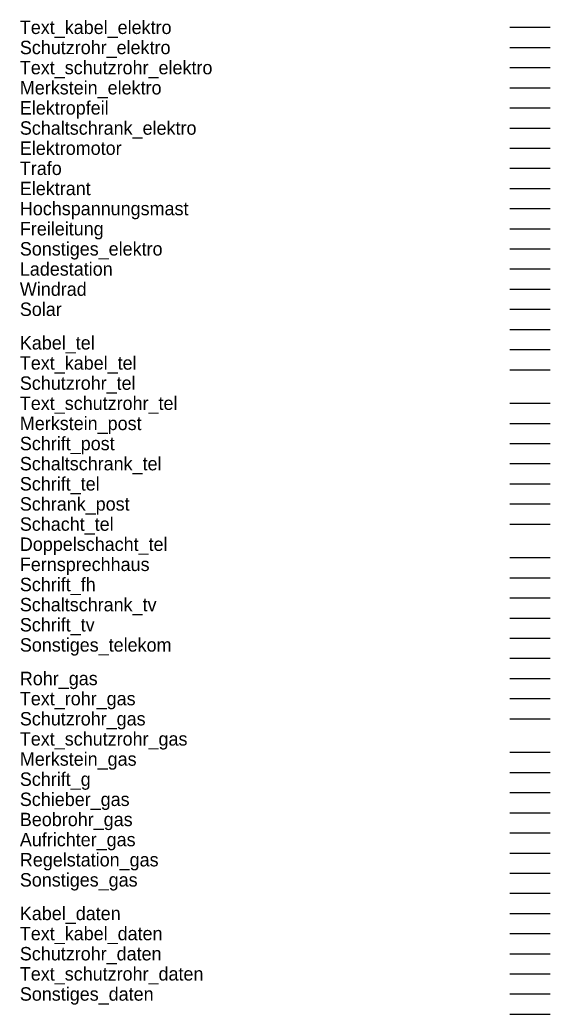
# Model space of a CAD drawing. Extents: x 0 to 177, y -135 to 1.
# Drawn here: x 83.5 to 123, y -133 to -58.9 of the extents above; entities that cross this region are included whole.
import ezdxf

# ---------------------------------------------------------------- set-up
doc = ezdxf.new("R2010")
doc.units = 0
for name, color, linetype in [('Ampel', 7, 'Continuous'), ('Aufrichter_gas', 7, 'Continuous'), ('Beobrohr_gas', 7, 'Continuous'), ('Bodenleuchte', 7, 'Continuous'), ('Doppelschacht_fw', 7, 'Continuous'), ('Doppelschacht_tel', 7, 'Continuous'), ('Elektrant', 7, 'Continuous'), ('Elektromotor', 7, 'Continuous'), ('Elektropfeil', 7, 'Continuous'), ('Fernsprechhaus', 7, 'Continuous'), ('Freileitung', 7, 'Continuous'), ('Haengelampe', 7, 'Continuous'), ('Hochspannungsmast', 7, 'Continuous'), ('Hoehe_el_symbol', 7, 'Continuous'), ('Hoehe_el_zahl', 7, 'Continuous'), ('Hoehe_first_symbol', 7, 'Continuous'), ('Hoehe_first_zahl', 7, 'Continuous'), ('Hoehe_objekt_zahl', 7, 'Continuous'), ('Hoehe_tel_symbol', 7, 'Continuous'), ('Hoehe_tel_zahl', 7, 'Continuous'), ('Hoehe_trauf_symbol', 7, 'Continuous'), ('Hoehe_trauf_zahl', 7, 'Continuous'), ('Hoehe_wasser_symbol', 7, 'Continuous'), ('Hoehe_wasser_zahl', 7, 'Continuous'), ('Hoehenpunkt_symbol', 7, 'Continuous'), ('Hoehenpunkt_zahl', 7, 'Continuous'), ('Kabel_daten', 7, 'Continuous'), ('Kabel_leucht', 7, 'Continuous'), ('Kabel_lsa', 7, 'Continuous'), ('Kabel_tel', 7, 'Continuous'), ('Ladestation', 7, 'Continuous'), ('Lampe_betonmast', 7, 'Continuous'), ('Lampe_holzmast', 7, 'Continuous'), ('Lampe_plastemast', 7, 'Continuous'), ('Lampe_stahlgittermast', 7, 'Continuous'), ('Lampe_stahlrohrmast', 7, 'Continuous'), ('Lampennummer', 7, 'Continuous'), ('Merkstein_elektro', 7, 'Continuous'), ('Merkstein_gas', 7, 'Continuous'), ('Merkstein_post', 7, 'Continuous'), ('Objektlampe', 7, 'Continuous'), ('Profil', 7, 'Continuous'), ('Regelstation_gas', 7, 'Continuous'), ('Rohr_brauchw', 7, 'Continuous'), ('Rohr_gas', 7, 'Continuous'), ('Rohr_ueber_fw', 7, 'Continuous'), ('Rohr_ueber_fw_text', 7, 'Continuous'), ('Rohr_unter_fw', 7, 'Continuous'), ('Rohr_unter_fw_text', 7, 'Continuous'), ('Schacht_e_fw', 7, 'Continuous'), ('Schacht_e_lsa', 7, 'Continuous'), ('Schacht_tel', 7, 'Continuous'), ('Schaltschrank_elektro', 7, 'Continuous'), ('Schaltschrank_leucht', 7, 'Continuous'), ('Schaltschrank_leucht_nr', 7, 'Continuous'), ('Schaltschrank_tel', 7, 'Continuous'), ('Schaltschrank_tv', 7, 'Continuous'), ('Schieber_fw', 7, 'Continuous'), ('Schieber_gas', 7, 'Continuous'), ('Schrank_post', 7, 'Continuous'), ('Schrift_fh', 7, 'Continuous'), ('Schrift_fw', 7, 'Continuous'), ('Schrift_g', 7, 'Continuous'), ('Schrift_lsa', 7, 'Continuous'), ('Schrift_post', 7, 'Continuous'), ('Schrift_tel', 7, 'Continuous'), ('Schrift_tv', 7, 'Continuous'), ('Schutzrohr_daten', 7, 'Continuous'), ('Schutzrohr_elektro', 7, 'Continuous'), ('Schutzrohr_gas', 7, 'Continuous'), ('Schutzrohr_leucht', 7, 'Continuous'), ('Schutzrohr_lsa', 7, 'Continuous'), ('Schutzrohr_tel', 7, 'Continuous'), ('Solar', 7, 'Continuous'), ('Sonstiges_daten', 7, 'Continuous'), ('Sonstiges_elektro', 7, 'Continuous'), ('Sonstiges_fw', 7, 'Continuous'), ('Sonstiges_gas', 7, 'Continuous'), ('Sonstiges_telekom', 7, 'Continuous'), ('Text_kabel_daten', 7, 'Continuous'), ('Text_kabel_elektro', 7, 'Continuous'), ('Text_kabel_leucht', 7, 'Continuous'), ('Text_kabel_lsa', 7, 'Continuous'), ('Text_kabel_tel', 7, 'Continuous'), ('Text_rohr_brauchw', 7, 'Continuous'), ('Text_rohr_gas', 7, 'Continuous'), ('Text_schutzrohr_daten', 7, 'Continuous'), ('Text_schutzrohr_elektro', 7, 'Continuous'), ('Text_schutzrohr_gas', 7, 'Continuous'), ('Text_schutzrohr_leucht', 7, 'Continuous'), ('Text_schutzrohr_lsa', 7, 'Continuous'), ('Text_schutzrohr_tel', 7, 'Continuous'), ('Trafo', 7, 'Continuous'), ('Wandlampe', 7, 'Continuous'), ('Windrad', 7, 'Continuous')]:
    doc.layers.add(name, color=color, linetype=linetype)

msp = doc.modelspace()

# ---------------------------------------------------------------- linework, layer by layer
at = {"layer": 'Ampel'}
msp.add_line((120, -96.5), (123, -96.5), dxfattribs=at)
at = {"layer": 'Bodenleuchte'}
msp.add_line((120, -79), (123, -79), dxfattribs=at)
at = {"layer": 'Doppelschacht_fw'}
msp.add_line((120, -106.5), (123, -106.5), dxfattribs=at)
at = {"layer": 'Haengelampe'}
msp.add_line((120, -80.5), (123, -80.5), dxfattribs=at)
at = {"layer": 'Hoehe_el_symbol'}
msp.add_line((120, -128.5), (123, -128.5), dxfattribs=at)
at = {"layer": 'Hoehe_el_zahl'}
msp.add_line((120, -130), (123, -130), dxfattribs=at)
at = {"layer": 'Hoehe_first_symbol'}
msp.add_line((120, -125.5), (123, -125.5), dxfattribs=at)
at = {"layer": 'Hoehe_first_zahl'}
msp.add_line((120, -127), (123, -127), dxfattribs=at)
at = {"layer": 'Hoehe_objekt_zahl'}
msp.add_line((120, -118), (123, -118), dxfattribs=at)
at = {"layer": 'Hoehe_tel_symbol'}
msp.add_line((120, -131.5), (123, -131.5), dxfattribs=at)
at = {"layer": 'Hoehe_tel_zahl'}
msp.add_line((120, -133), (123, -133), dxfattribs=at)
at = {"layer": 'Hoehe_trauf_symbol'}
msp.add_line((120, -122.5), (123, -122.5), dxfattribs=at)
at = {"layer": 'Hoehe_trauf_zahl'}
msp.add_line((120, -124), (123, -124), dxfattribs=at)
at = {"layer": 'Hoehe_wasser_symbol'}
msp.add_line((120, -119.5), (123, -119.5), dxfattribs=at)
at = {"layer": 'Hoehe_wasser_zahl'}
msp.add_line((120, -121), (123, -121), dxfattribs=at)
at = {"layer": 'Hoehenpunkt_symbol'}
msp.add_line((120, -115), (123, -115), dxfattribs=at)
at = {"layer": 'Hoehenpunkt_zahl'}
msp.add_line((120, -116.5), (123, -116.5), dxfattribs=at)
at = {"layer": 'Kabel_leucht'}
msp.add_line((120, -62.5), (123, -62.5), dxfattribs=at)
at = {"layer": 'Kabel_lsa'}
msp.add_line((120, -87.5), (123, -87.5), dxfattribs=at)
at = {"layer": 'Lampe_betonmast'}
msp.add_line((120, -71.5), (123, -71.5), dxfattribs=at)
at = {"layer": 'Lampe_holzmast'}
msp.add_line((120, -73), (123, -73), dxfattribs=at)
at = {"layer": 'Lampe_plastemast'}
msp.add_line((120, -77.5), (123, -77.5), dxfattribs=at)
at = {"layer": 'Lampe_stahlgittermast'}
msp.add_line((120, -76), (123, -76), dxfattribs=at)
at = {"layer": 'Lampe_stahlrohrmast'}
msp.add_line((120, -74.5), (123, -74.5), dxfattribs=at)
at = {"layer": 'Lampennummer'}
msp.add_line((120, -85), (123, -85), dxfattribs=at)
at = {"layer": 'Objektlampe'}
msp.add_line((120, -83.5), (123, -83.5), dxfattribs=at)
at = {"layer": 'Profil'}
msp.add_line((120, -113.5), (123, -113.5), dxfattribs=at)
at = {"layer": 'Rohr_brauchw'}
msp.add_line((120, -59.5), (123, -59.5), dxfattribs=at)
at = {"layer": 'Rohr_ueber_fw'}
msp.add_line((120, -99), (123, -99), dxfattribs=at)
at = {"layer": 'Rohr_ueber_fw_text'}
msp.add_line((120, -100.5), (123, -100.5), dxfattribs=at)
at = {"layer": 'Rohr_unter_fw'}
msp.add_line((120, -102), (123, -102), dxfattribs=at)
at = {"layer": 'Rohr_unter_fw_text'}
msp.add_line((120, -103.5), (123, -103.5), dxfattribs=at)
at = {"layer": 'Schacht_e_fw'}
msp.add_line((120, -105), (123, -105), dxfattribs=at)
at = {"layer": 'Schacht_e_lsa'}
msp.add_line((120, -93.5), (123, -93.5), dxfattribs=at)
at = {"layer": 'Schaltschrank_leucht'}
msp.add_line((120, -68.5), (123, -68.5), dxfattribs=at)
at = {"layer": 'Schaltschrank_leucht_nr'}
msp.add_line((120, -70), (123, -70), dxfattribs=at)
at = {"layer": 'Schieber_fw'}
msp.add_line((120, -109.5), (123, -109.5), dxfattribs=at)
at = {"layer": 'Schrift_fw'}
msp.add_line((120, -108), (123, -108), dxfattribs=at)
at = {"layer": 'Schrift_lsa'}
msp.add_line((120, -95), (123, -95), dxfattribs=at)
at = {"layer": 'Schutzrohr_leucht'}
msp.add_line((120, -65.5), (123, -65.5), dxfattribs=at)
at = {"layer": 'Schutzrohr_lsa'}
msp.add_line((120, -90.5), (123, -90.5), dxfattribs=at)
at = {"layer": 'Sonstiges_fw'}
msp.add_line((120, -111), (123, -111), dxfattribs=at)
at = {"layer": 'Text_kabel_leucht'}
msp.add_line((120, -64), (123, -64), dxfattribs=at)
at = {"layer": 'Text_kabel_lsa'}
msp.add_line((120, -89), (123, -89), dxfattribs=at)
at = {"layer": 'Text_rohr_brauchw'}
msp.add_line((120, -61), (123, -61), dxfattribs=at)
at = {"layer": 'Text_schutzrohr_leucht'}
msp.add_line((120, -67), (123, -67), dxfattribs=at)
at = {"layer": 'Text_schutzrohr_lsa'}
msp.add_line((120, -92), (123, -92), dxfattribs=at)
at = {"layer": 'Wandlampe'}
msp.add_line((120, -82), (123, -82), dxfattribs=at)

# ---------------------------------------------------------------- texts
at = {"layer": 'Aufrichter_gas'}
msp.add_text('Aufrichter_gas', height=1, dxfattribs=at).set_placement((83.5, -120.5))
at = {"layer": 'Beobrohr_gas'}
msp.add_text('Beobrohr_gas', height=1, dxfattribs=at).set_placement((83.5, -119))
at = {"layer": 'Doppelschacht_tel'}
msp.add_text('Doppelschacht_tel', height=1, dxfattribs=at).set_placement((83.5, -98.5))
at = {"layer": 'Elektrant'}
msp.add_text('Elektrant', height=1, dxfattribs=at).set_placement((83.5, -72))
at = {"layer": 'Elektromotor'}
msp.add_text('Elektromotor', height=1, dxfattribs=at).set_placement((83.5, -69))
at = {"layer": 'Elektropfeil'}
msp.add_text('Elektropfeil', height=1, dxfattribs=at).set_placement((83.5, -66))
at = {"layer": 'Fernsprechhaus'}
msp.add_text('Fernsprechhaus', height=1, dxfattribs=at).set_placement((83.5, -100))
at = {"layer": 'Freileitung'}
msp.add_text('Freileitung', height=1, dxfattribs=at).set_placement((83.5, -75))
at = {"layer": 'Hochspannungsmast'}
msp.add_text('Hochspannungsmast', height=1, dxfattribs=at).set_placement((83.5, -73.5))
at = {"layer": 'Kabel_daten'}
msp.add_text('Kabel_daten', height=1, dxfattribs=at).set_placement((83.5, -126))
at = {"layer": 'Kabel_tel'}
msp.add_text('Kabel_tel', height=1, dxfattribs=at).set_placement((83.5, -83.5))
at = {"layer": 'Ladestation'}
msp.add_text('Ladestation', height=1, dxfattribs=at).set_placement((83.5, -78))
at = {"layer": 'Merkstein_elektro'}
msp.add_text('Merkstein_elektro', height=1, dxfattribs=at).set_placement((83.5, -64.5))
at = {"layer": 'Merkstein_gas'}
msp.add_text('Merkstein_gas', height=1, dxfattribs=at).set_placement((83.5, -114.5))
at = {"layer": 'Merkstein_post'}
msp.add_text('Merkstein_post', height=1, dxfattribs=at).set_placement((83.5, -89.5))
at = {"layer": 'Regelstation_gas'}
msp.add_text('Regelstation_gas', height=1, dxfattribs=at).set_placement((83.5, -122))
at = {"layer": 'Rohr_gas'}
msp.add_text('Rohr_gas', height=1, dxfattribs=at).set_placement((83.5, -108.5))
at = {"layer": 'Schacht_tel'}
msp.add_text('Schacht_tel', height=1, dxfattribs=at).set_placement((83.5, -97))
at = {"layer": 'Schaltschrank_elektro'}
msp.add_text('Schaltschrank_elektro', height=1, dxfattribs=at).set_placement((83.5, -67.5))
at = {"layer": 'Schaltschrank_tel'}
msp.add_text('Schaltschrank_tel', height=1, dxfattribs=at).set_placement((83.5, -92.5))
at = {"layer": 'Schaltschrank_tv'}
msp.add_text('Schaltschrank_tv', height=1, dxfattribs=at).set_placement((83.5, -103))
at = {"layer": 'Schieber_gas'}
msp.add_text('Schieber_gas', height=1, dxfattribs=at).set_placement((83.5, -117.5))
at = {"layer": 'Schrank_post'}
msp.add_text('Schrank_post', height=1, dxfattribs=at).set_placement((83.5, -95.5))
at = {"layer": 'Schrift_fh'}
msp.add_text('Schrift_fh', height=1, dxfattribs=at).set_placement((83.5, -101.5))
at = {"layer": 'Schrift_g'}
msp.add_text('Schrift_g', height=1, dxfattribs=at).set_placement((83.5, -116))
at = {"layer": 'Schrift_post'}
msp.add_text('Schrift_post', height=1, dxfattribs=at).set_placement((83.5, -91))
at = {"layer": 'Schrift_tel'}
msp.add_text('Schrift_tel', height=1, dxfattribs=at).set_placement((83.5, -94))
at = {"layer": 'Schrift_tv'}
msp.add_text('Schrift_tv', height=1, dxfattribs=at).set_placement((83.5, -104.5))
at = {"layer": 'Schutzrohr_daten'}
msp.add_text('Schutzrohr_daten', height=1, dxfattribs=at).set_placement((83.5, -129))
at = {"layer": 'Schutzrohr_elektro'}
msp.add_text('Schutzrohr_elektro', height=1, dxfattribs=at).set_placement((83.5, -61.5))
at = {"layer": 'Schutzrohr_gas'}
msp.add_text('Schutzrohr_gas', height=1, dxfattribs=at).set_placement((83.5, -111.5))
at = {"layer": 'Schutzrohr_tel'}
msp.add_text('Schutzrohr_tel', height=1, dxfattribs=at).set_placement((83.5, -86.5))
at = {"layer": 'Solar'}
msp.add_text('Solar', height=1, dxfattribs=at).set_placement((83.5, -81))
at = {"layer": 'Sonstiges_daten'}
msp.add_text('Sonstiges_daten', height=1, dxfattribs=at).set_placement((83.5, -132))
at = {"layer": 'Sonstiges_elektro'}
msp.add_text('Sonstiges_elektro', height=1, dxfattribs=at).set_placement((83.5, -76.5))
at = {"layer": 'Sonstiges_gas'}
msp.add_text('Sonstiges_gas', height=1, dxfattribs=at).set_placement((83.5, -123.5))
at = {"layer": 'Sonstiges_telekom'}
msp.add_text('Sonstiges_telekom', height=1, dxfattribs=at).set_placement((83.5, -106))
at = {"layer": 'Text_kabel_daten'}
msp.add_text('Text_kabel_daten', height=1, dxfattribs=at).set_placement((83.5, -127.5))
at = {"layer": 'Text_kabel_elektro'}
msp.add_text('Text_kabel_elektro', height=1, dxfattribs=at).set_placement((83.5, -60))
at = {"layer": 'Text_kabel_tel'}
msp.add_text('Text_kabel_tel', height=1, dxfattribs=at).set_placement((83.5, -85))
at = {"layer": 'Text_rohr_gas'}
msp.add_text('Text_rohr_gas', height=1, dxfattribs=at).set_placement((83.5, -110))
at = {"layer": 'Text_schutzrohr_daten'}
msp.add_text('Text_schutzrohr_daten', height=1, dxfattribs=at).set_placement((83.5, -130.5))
at = {"layer": 'Text_schutzrohr_elektro'}
msp.add_text('Text_schutzrohr_elektro', height=1, dxfattribs=at).set_placement((83.5, -63))
at = {"layer": 'Text_schutzrohr_gas'}
msp.add_text('Text_schutzrohr_gas', height=1, dxfattribs=at).set_placement((83.5, -113))
at = {"layer": 'Text_schutzrohr_tel'}
msp.add_text('Text_schutzrohr_tel', height=1, dxfattribs=at).set_placement((83.5, -88))
at = {"layer": 'Trafo'}
msp.add_text('Trafo', height=1, dxfattribs=at).set_placement((83.5, -70.5))
at = {"layer": 'Windrad'}
msp.add_text('Windrad', height=1, dxfattribs=at).set_placement((83.5, -79.5))

doc.saveas('drawing.dxf')
